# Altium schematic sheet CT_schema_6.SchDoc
size 581 x 363 mm
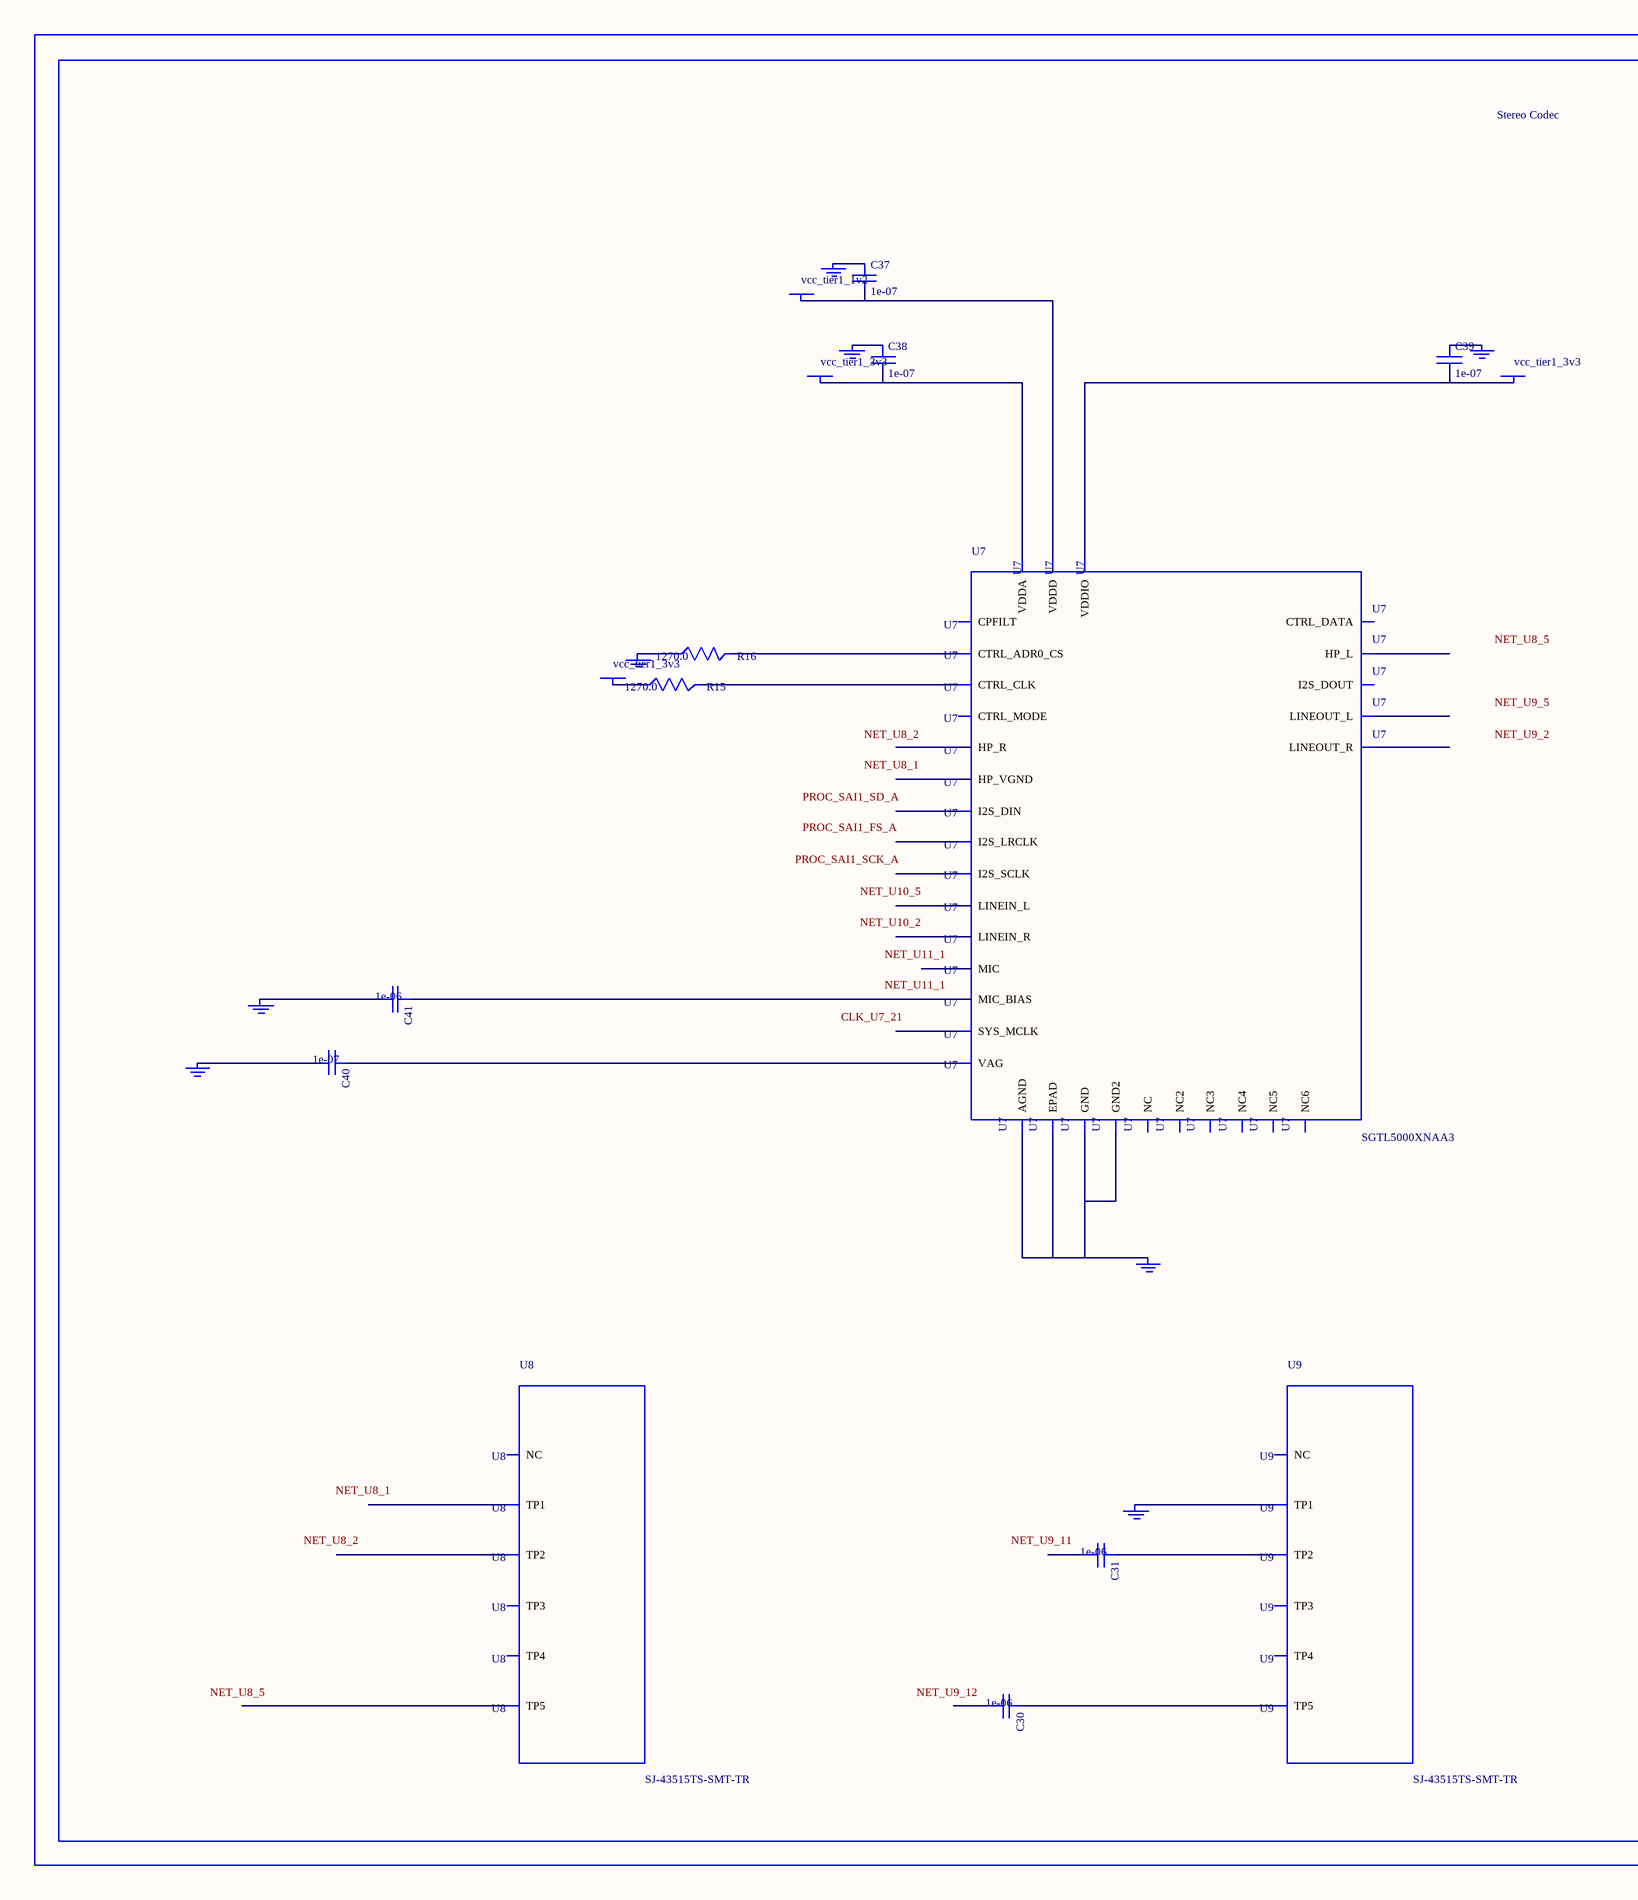
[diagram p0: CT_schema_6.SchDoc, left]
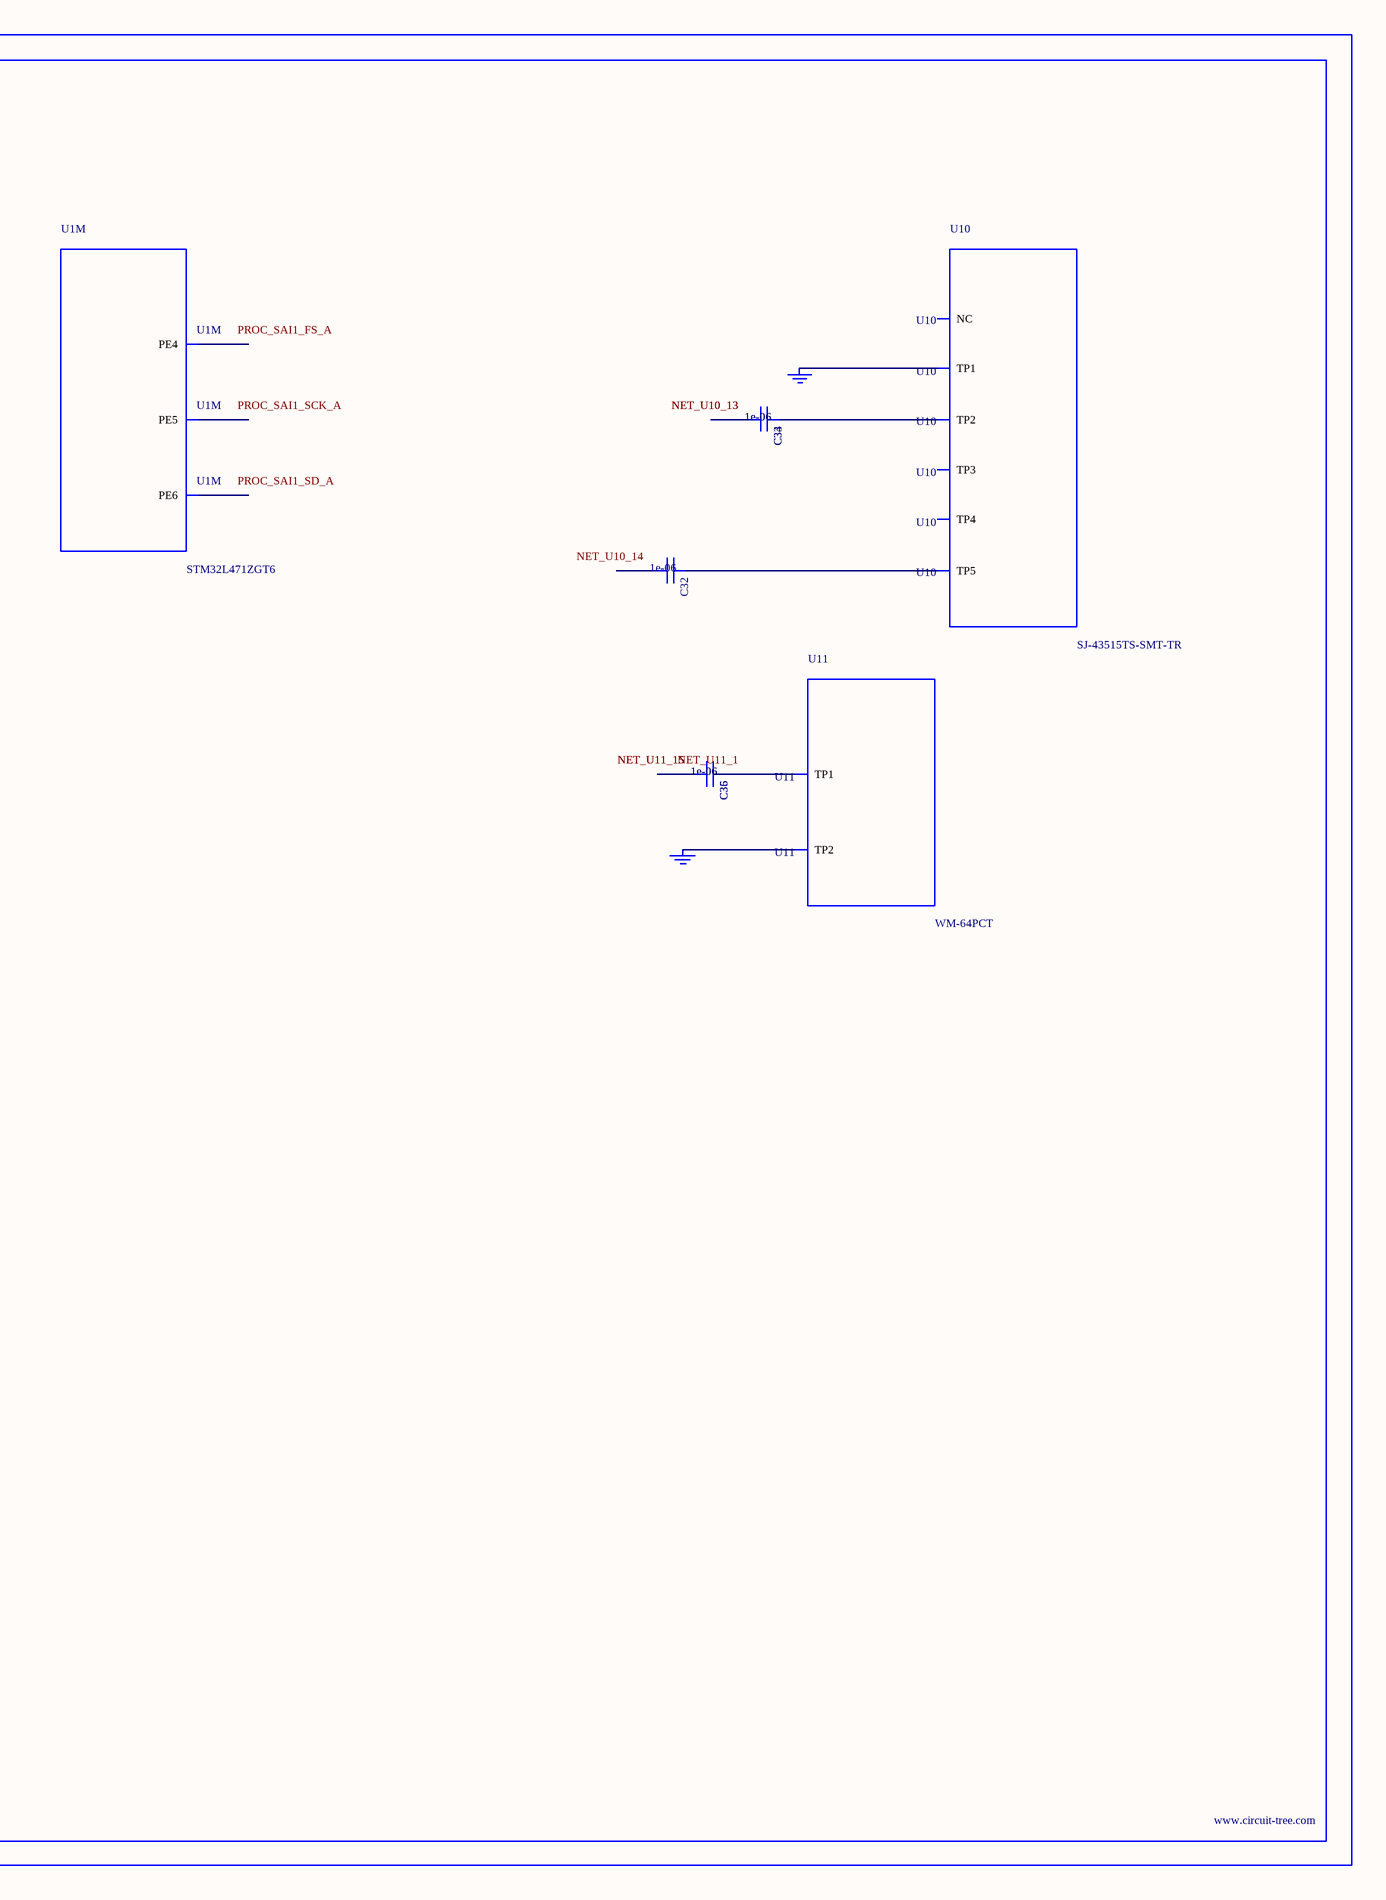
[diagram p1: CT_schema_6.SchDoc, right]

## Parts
BORDER5  (no value)
C30  1e-06  [C0603]
C31  1e-06  [C0603]
C32  1e-06  [C0603]
C33  1e-06  [C0603]
C34  1e-06  [C0603]
C35  1e-06  [C0603]
C36  1e-06  [C0603]
C37  1e-07  [C0402]
C38  1e-07  [C0402]
C39  1e-07  [C0402]
C40  1e-07  [C0402]
C41  1e-06  [C0603]
GND_INSTANCE_5_0  (no value)
GND_INSTANCE_5_1  (no value)
GND_INSTANCE_5_2  (no value)
GND_INSTANCE_5_3  (no value)
GND_INSTANCE_5_4  (no value)
GND_INSTANCE_5_5  (no value)
GND_INSTANCE_5_6  (no value)
GND_INSTANCE_5_7  (no value)
GND_INSTANCE_5_8  (no value)
GND_INSTANCE_5_9  (no value)
GND_INSTANCE_5_10  (no value)
POWER_INSTANCE_5_0  vcc_tier1_3v3
POWER_INSTANCE_5_1  vcc_tier1_3v3
POWER_INSTANCE_5_2  vcc_tier1_3v3
POWER_INSTANCE_5_3  vcc_tier1_1v2
R15  1270.0  [R0603]
R16  1270.0  [R0603]
U1  STM32L471ZGT6  [LQFP144]  (part M of 14)
U7  SGTL5000XNAA3  [QFN-32]
U8  SJ-43515TS-SMT-TR  [SJ-43515TS-SMT-TR]
U9  SJ-43515TS-SMT-TR  [SJ-43515TS-SMT-TR]
U10  SJ-43515TS-SMT-TR  [SJ-43515TS-SMT-TR]
U11  WM-64PCT  [WM-64PC]

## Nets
NetC30_1: C30.1 U9.5(TP5)
NetC31_1: C31.1 U9.2(TP2)
NetC32_1: C32.1 U10.5(TP5)
NetC33_1: C33.1 C34.1 U10.2(TP2)
NetC33_2: C33.2 C34.2
NetC35_1: C35.1 C36.1 U11.1(TP1)
NetC35_2: C35.2 C36.2
NetC37_1: C37.1 GND_INSTANCE_5_5.0(GND)
NetC37_2: C37.2 POWER_INSTANCE_5_3.0(PWR) U7.30(VDDD)
NetC38_1: C38.1 GND_INSTANCE_5_1.0(GND)
NetC38_2: C38.2 POWER_INSTANCE_5_0.0(PWR) U7.5(VDDA)
NetC39_1: C39.1 GND_INSTANCE_5_4.0(GND)
NetC39_2: C39.2 POWER_INSTANCE_5_1.0(PWR) U7.20(VDDIO)
NetC40_1: C40.1 U7.10(VAG)
NetC40_2: C40.2 GND_INSTANCE_5_2.0(GND)
NetC41_1: C41.1 U7.16(MIC_BIAS)
NetC41_2: C41.2 GND_INSTANCE_5_3.0(GND)
NetGND_INSTANCE_5_0_0: GND_INSTANCE_5_0.0(GND) U7.1(GND) U7.3(GND2) U7.7(AGND) U7.EXP(EPAD)
NetGND_INSTANCE_5_6_0: GND_INSTANCE_5_6.0(GND) R16.1
NetGND_INSTANCE_5_7_0: GND_INSTANCE_5_7.0(GND) U9.1(TP1)
NetGND_INSTANCE_5_8_0: GND_INSTANCE_5_8.0(GND) GND_INSTANCE_5_9.0(GND) U10.1(TP1)
NetGND_INSTANCE_5_10_0: GND_INSTANCE_5_10.0(GND) U11.2(TP2)
NetPOWER_INSTANCE_5_2_0: POWER_INSTANCE_5_2.0(PWR) R15.1
NetR15_2: R15.2 U7.29(CTRL_CLK)
NetR16_2: R16.2 U7.31(CTRL_ADR0_CS)

Not connected (* = marked no-connect by the designer): C30 2; C31 2; C32 2; U1 3(PE4) 4(PE5) 5(PE6); U7 2(HP_R) 4(HP_VGND) 6(HP_L) 8(NC) 9(NC2) 11(LINEOUT_R) 12(LINEOUT_L) 13(LINEIN_R) 14(LINEIN_L) 15(MIC) 17(NC3) 18(CPFILT) 19(NC4) 21(SYS_MCLK) 22(NC5) 23(I2S_LRCLK) 24(I2S_SCLK) 25(I2S_DOUT) 26(I2S_DIN) 27(CTRL_DATA) 28(NC6) 32(CTRL_MODE); U8 1(TP1) 2(TP2) 3(TP3) 4(TP4) 5(TP5) 6(NC); U9 3(TP3) 4(TP4) 6(NC); U10 3(TP3) 4(TP4) 6(NC)

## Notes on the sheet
- Labels drawn without touching a wire or pin: CLK_U7_21, NET_U8_1, NET_U8_2, NET_U8_5, NET_U9_2, NET_U9_5, NET_U9_11, NET_U9_12, NET_U10_2, NET_U10_5, NET_U10_14, NET_U11_1, PROC_SAI1_FS_A, PROC_SAI1_SCK_A, PROC_SAI1_SD_A

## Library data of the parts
BORDER5 = BORDER_PAGE5
C30-C36 C41 = C0603C105K3RACTU
C37-C40 = C0402C104K3RACTU
GND_INSTANCE_5_0-GND_INSTANCE_5_10 = GND
POWER_INSTANCE_5_0-POWER_INSTANCE_5_3 = PWR
R15 R16 = RC0603FR-071K27L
